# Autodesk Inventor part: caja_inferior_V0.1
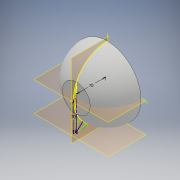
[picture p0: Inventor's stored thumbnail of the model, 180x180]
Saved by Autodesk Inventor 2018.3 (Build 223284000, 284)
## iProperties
Created: 2019-04
Part Number: caja_inferior_V0.1
Material: Generic
Document SubType Name: Modeling
Designer: Antonio Gordillo
Density: 1 g/cm^3
Appearance: Default
Author: Antonio Gordillo
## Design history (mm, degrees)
sketch "Sketch1"
  geometry: L1 (0, 123.64)-(0, -108.107) reference; L2 (-123.64, 0)-(108.107, 0) reference; L3 (-73, 32.726)-(-73, 0); L4 (0, -108.107)-(0, 123.64) reference; L5 (-73, 0)-(-80, 0); A1 r 80 centre (0, 0) between (0, 80) and (-80, 0); A2 r 80 centre (0, 0) between (0, 80) and (-80, 0)
  constraints: 5 point on circle, 5 point on line, 4 end point, 2 centre point, 1 collinear, 1 concentric, 1 parallel
  dimensions: "diam_ext" = 160 diameter of A1; "d24" = 7 distance from line of L5.end L3
sketch "Sketch2"
  geometry: L1 (0, -17.382)-(0, 104.294) reference; L2 (0, 77)-(0, 0); L3 (0, 0)-(-77, 0); L4 (-104.294, 0)-(17.382, 0) reference; L5 (-68, 36.125)-(-68, 0); L6 (-68, 0)-(-77, 0); L7 (-68, 0)-(-68, 36.125); A1 r 77 centre (0, 0) between (0, 77) and (-77, 0); A2 r 77 centre (0, 0) between (-68, 36.125) and (-77, 0); 1 further point
  constraints: 10 end point, 5 point on circle, 3 point on line, 2 centre point, 2 collinear, 2 perpendicular, 1 concentric
  dimensions: "d26" = 77 radius of A1; "d27" = 9 distance from line of L5 L3.end
workplane "Work Plane1"
sketch "Sketch3"
  geometry: L1 (25, 55)-(-25, 55); L2 (-28, 52)-(-28, -27); L3 (-25, -30)-(25, -30); L4 (28, -27)-(28, 52); L5 (40.07, 0)-(-40.07, 0) reference; L6 (0, -47.87)-(0, 72.87) reference; C1 r 1.375 at (24.5, 51.5); C2 r 1.375 at (24.5, -6.5); C3 r 1.375 at (-24.5, 51.5); C4 r 1.375 at (-24.5, -6.5); A1 r 3 centre (25, 52) between (28, 52) and (25, 55); A2 r 3 centre (25, -27) between (25, -30) and (28, -27); A3 r 3 centre (-25, -27) between (-28, -27) and (-25, -30); A4 r 3 centre (-25, 52) between (-25, 55) and (-28, 52); 4 further points
  constraints: 8 centre point, 8 end point, 8 point on circle, 8 tangent, 6 point on line, 3 equal radius, 2 horizontal, 2 parallel, 1 perpendicular, 1 vertical, 7 other
  dimensions: "largo_pi" = 85 distance of point (28, -30) point (28, 55); "ancho_pi" = 56 distance of point (-28, -30) point (28, -30); "d9" = 3 radius of A1 (derived); "diam_tornillo_pi" = 2.75 diameter of C1; "d11" = 3.5 distance from line of L4 C1.centre; "d12" = 3.5 distance from line of L1 C1.centre; "d15" = 58 distance of C1.centre C2.centre; "d18" = 49 distance of C1.centre C3.centre; "d21" = 55 distance between parallel lines of L5 L1
extrude "Extrusion1" new body sketch "Sketch3" distance "d22" = 4; taper "d23" = 0 deg
revolve "Revolution3" stored, may be unused: angle "d25" = 180 deg
revolve "Revolution6" stored, may be unused: angle "d30" = 180 deg
sketch "Sketch4"
  geometry: L1 (-73, -32.726)-(-73, 32.726) reference; L2 (-73, 0)-(-73, -70); L3 (-73, 0)-(-3, 0); L4 (-3, 0)-(-73, -70); L5 (-73, -70)-(-48.796, -70); L6 (-48.796, -70)-(-40.773, -55.902); L7 (-40.773, -55.902)-(-46.701, -46.954); L8 (-46.701, -46.954)-(-48.328, -45.328); L9 (-73, -70)-(-73, -45.796); L10 (-73, -45.796)-(-58.902, -37.773); L11 (-58.902, -37.773)-(-49.954, -43.701); L12 (-49.954, -43.701)-(-48.328, -45.328); L13 (-73, -32.726)-(-73, 32.726) reference; L14 (-68, 36.125)-(-68, -36.125) reference; L15 (0, 77)-(0, -77) reference; A1 r 80 centre (0, 0) between (0, 80) and (0, -80) reference; A2 r 77 centre (0, 0) between (0, 77) and (0, -77) reference; A3 r 77 centre (0, 0) between (-62.582, -44.861) and (-48.177, -60.067); A4 r 77 centre (0, 0) between (-62.582, -44.861) and (-55.899, -52.956); A5 r 77 centre (0, 0) between (-55.899, -52.956) and (-48.177, -60.067); 6 further points
  constraints: 8 point on circle, 6 end point, 3 centre point, 3 symmetric about line, 2 horizontal, 1 collinear, 1 midpoint, 1 point on line, 12 other
  dimensions: "d31" = 70 distance of L2.start L2.end; "d32" = 70 distance of L2.start L3.end
  node "Projected Loop1"
  node "Projected Loop2"
workplane "Work Plane2"
sketch "Sketch5"
  geometry: C1 r 2 at (0, 0); 2 further points
  constraints: 1 centre point, 1 coincident
  dimensions: "d33" = 4 diameter of C1
sketch "Sketch6"
  geometry: L1 (-68, 36.125)-(-68, -36.125) reference; L2 (0, 77)-(0, -77) reference; L3 (-67, -37.947)-(-40, -37.947); L4 (-67, -37.947)-(-40, -37.947); L5 (-40, -27)-(-40, -30) reference; L6 (-40, -37.947)-(-40, -65.795); L7 (-67, -37.947)-(-40, -37.947); L8 (-40, -37.947)-(-40, -65.795); A1 r 77 centre (0, 0) between (-62.582, -44.861) and (-48.177, -60.067) reference; A2 r 77 centre (0, 0) between (0, 77) and (0, -77) reference; A3 r 77 centre (0, 0) between (-63.162, -44.04) and (-47.388, -60.691); A4 r 80 centre (0, 0) between (0, 80) and (0, -80) reference; A5 r 77 centre (0, 0) between (-67, -37.947) and (-40, -65.795); 4 further points
  constraints: 10 end point, 4 point on circle, 2 centre point, 2 collinear, 1 concentric, 1 horizontal, 1 point on line, 6 other
  dimensions: "d35" = 0 distance between parallel lines of L3 L4; "d36" = 90 deg angle of L3 L6; "d37" = 27 distance of L3.start L3.end
extrude "Extrusion2" join sketch "Sketch6" stored distance "d38" = 20; taper "d39" = 0 deg
body "Solid1"
node "pi3_base"
body "Solid3"
node "Projected Loop3"
